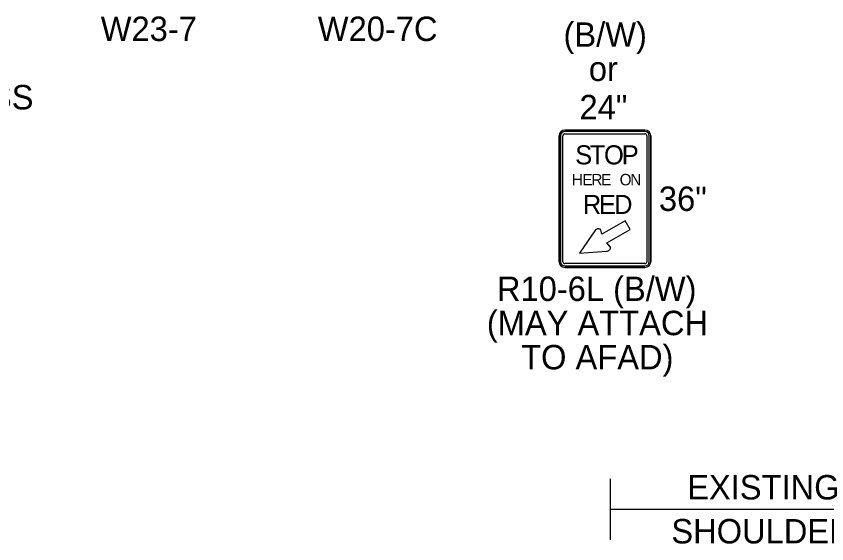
# Model space of a CAD drawing. Extents: x 99999.1 to 100095.7, y 99995 to 100010.7.
# Drawn here: x 100002.344 to 100005, y 100003.112 to 100004.84 of the extents above; entities that cross this region are included whole.
import ezdxf

# ---------------------------------------------------------------- set-up
doc = ezdxf.new("R2010")
doc.units = 0
doc.layers.add('TR_SN_ConstructionSigns', color=7, linetype='Continuous')
doc.layers.add('TR_WZ_WorkZoneDetails', color=7, linetype='Continuous')

msp = doc.modelspace()

# ---------------------------------------------------------------- linework, layer by layer
at = {"layer": 'TR_SN_ConstructionSigns'}
for p, q in [((100004.4041, 100004.4676), (100004.1416, 100004.4676)), ((100004.1416, 100004.4676), (100004.4041, 100004.4676)), ((100004.4041, 100004.4676), (100004.1416, 100004.4676)), ((100004.4041, 100004.4629), (100004.1416, 100004.4629)), ((100004.1416, 100004.4551), (100004.4041, 100004.4551)), ((100004.1229, 100004.4489), (100004.1229, 100004.0364)), ((100004.1229, 100004.0364), (100004.1229, 100004.4489)), ((100004.1229, 100004.4489), (100004.1229, 100004.0364)), ((100004.1276, 100004.4489), (100004.1276, 100004.0364)), ((100004.1354, 100004.0364), (100004.1354, 100004.4489)), ((100004.4104, 100004.4489), (100004.4104, 100004.0364)), ((100004.4182, 100004.0364), (100004.4182, 100004.4489)), ((100004.4229, 100004.0364), (100004.4229, 100004.4489)), ((100004.4229, 100004.4489), (100004.4229, 100004.0364)), ((100004.4229, 100004.0364), (100004.4229, 100004.4489)), ((100004.3396, 100004.1707), (100004.263, 100004.1265)), ((100004.356, 100004.1423), (100004.3396, 100004.1707)), ((100004.2424, 100004.1403), (100004.1898, 100004.0646)), ((100004.263, 100004.1265), (100004.2592, 100004.1391)), ((100004.2786, 100004.0976), (100004.356, 100004.1423)), ((100004.2909, 100004.0839), (100004.2786, 100004.0976)), ((100004.1898, 100004.0646), (100004.2776, 100004.0707)), ((100004.4041, 100004.0301), (100004.1416, 100004.0301)), ((100004.1416, 100004.0223), (100004.4041, 100004.0223)), ((100004.1416, 100004.0176), (100004.4041, 100004.0176)), ((100004.4041, 100004.0176), (100004.1416, 100004.0176)), ((100004.1416, 100004.0176), (100004.4041, 100004.0176))]:
    msp.add_line(p, q, dxfattribs=at)
for centre, radius, start, end in [((100004.1416, 100004.4489), 0.0187, 90, 180), ((100004.1416, 100004.4489), 0.0187, 90, 180), ((100004.1416, 100004.4489), 0.0187, 90, 180), ((100004.1416, 100004.4489), 0.0141, 90, 180), ((100004.1416, 100004.4489), 0.00625, 90, 180), ((100004.4041, 100004.4489), 0.0187, 0, 90), ((100004.4041, 100004.4489), 0.0187, 0, 90), ((100004.4041, 100004.4489), 0.0187, 0, 90), ((100004.4041, 100004.4489), 0.0141, 0, 90), ((100004.4041, 100004.4489), 0.00625, 0, 90), ((100004.1416, 100004.0364), 0.0187, 180, 270), ((100004.1416, 100004.0364), 0.0187, 180, 270), ((100004.1416, 100004.0364), 0.0187, 180, 270), ((100004.1416, 100004.0364), 0.0141, 180, 270), ((100004.1416, 100004.0364), 0.00625, 180, 270), ((100004.4041, 100004.0364), 0.0187, 270, 0), ((100004.4041, 100004.0364), 0.0187, 270, 0), ((100004.4041, 100004.0364), 0.0187, 270, 0), ((100004.4041, 100004.0364), 0.0141, 270, 0), ((100004.4041, 100004.0364), 0.00625, 270, 0)]:
    msp.add_arc(centre, radius, start, end, dxfattribs=at)
for centre, major_axis, start_param, end_param in [((100004.2492, 100004.136), (0.00934, 0.00539), 5.977036, 8.198856), ((100004.2816, 100004.0789), (-0.00913, -0.00527), 0.771965, 3.092601)]:
    msp.add_ellipse(centre, major_axis=major_axis, ratio=0.700347, start_param=start_param, end_param=end_param, dxfattribs=at)
at = {"layer": 'TR_WZ_WorkZoneDetails'}
for p, q in [((100004.2907, 100003.1255), (100004.2907, 100003.3255)), ((100004.2907, 100003.2255), (100005.2907, 100003.2255))]:
    msp.add_line(p, q, dxfattribs=at)

# ---------------------------------------------------------------- texts
at = {"layer": 'TR_SN_ConstructionSigns'}
for s, p in [('W23-7', (100002.6204, 100004.7592)), ('W20-7C', (100003.3319, 100004.7592)), ('(B/W)', (100004.1371, 100004.7403)), ('or', (100004.2201, 100004.6283)), ('40 MPH OR LESS', (100001.5202, 100004.5352)), ('24"', (100004.1895, 100004.5026)), ('36"', (100004.4498, 100004.2026)), ('R10-6L (B/W)', (100003.919, 100003.9076)), ('(MAY ATTACH', (100003.8858, 100003.7956)), ('TO AFAD)', (100003.9982, 100003.6836))]:
    msp.add_text(s, height=0.08, rotation=360, dxfattribs=at).set_placement(p)
for s, height, p in [('S', 0.0625, (100004.1754, 100004.3551)), ('T', 0.0625, (100004.2229, 100004.3551)), ('O', 0.0625, (100004.2698, 100004.3551)), ('P', 0.0625, (100004.3279, 100004.3551)), ('H', 0.0375, (100004.1643, 100004.2864)), ('E', 0.0375, (100004.1988, 100004.2864)), ('R', 0.0375, (100004.2284, 100004.2864)), ('E', 0.0375, (100004.2603, 100004.2864)), ('O', 0.0375, (100004.3211, 100004.2864)), ('N', 0.0375, (100004.3559, 100004.2864)), ('R', 0.0625, (100004.2004, 100004.1926)), ('E', 0.0625, (100004.2535, 100004.1926)), ('D', 0.0625, (100004.3029, 100004.1926))]:
    msp.add_text(s, height=height, dxfattribs=at).set_placement(p)
at = {"layer": 'TR_WZ_WorkZoneDetails'}
for s, p in [('EXISTING', (100004.5424, 100003.2575)), ('SHOULDER', (100004.4905, 100003.1135))]:
    msp.add_text(s, height=0.08, rotation=360, dxfattribs=at).set_placement(p)

doc.saveas('drawing.dxf')
